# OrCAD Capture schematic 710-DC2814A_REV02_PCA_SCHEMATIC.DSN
size C
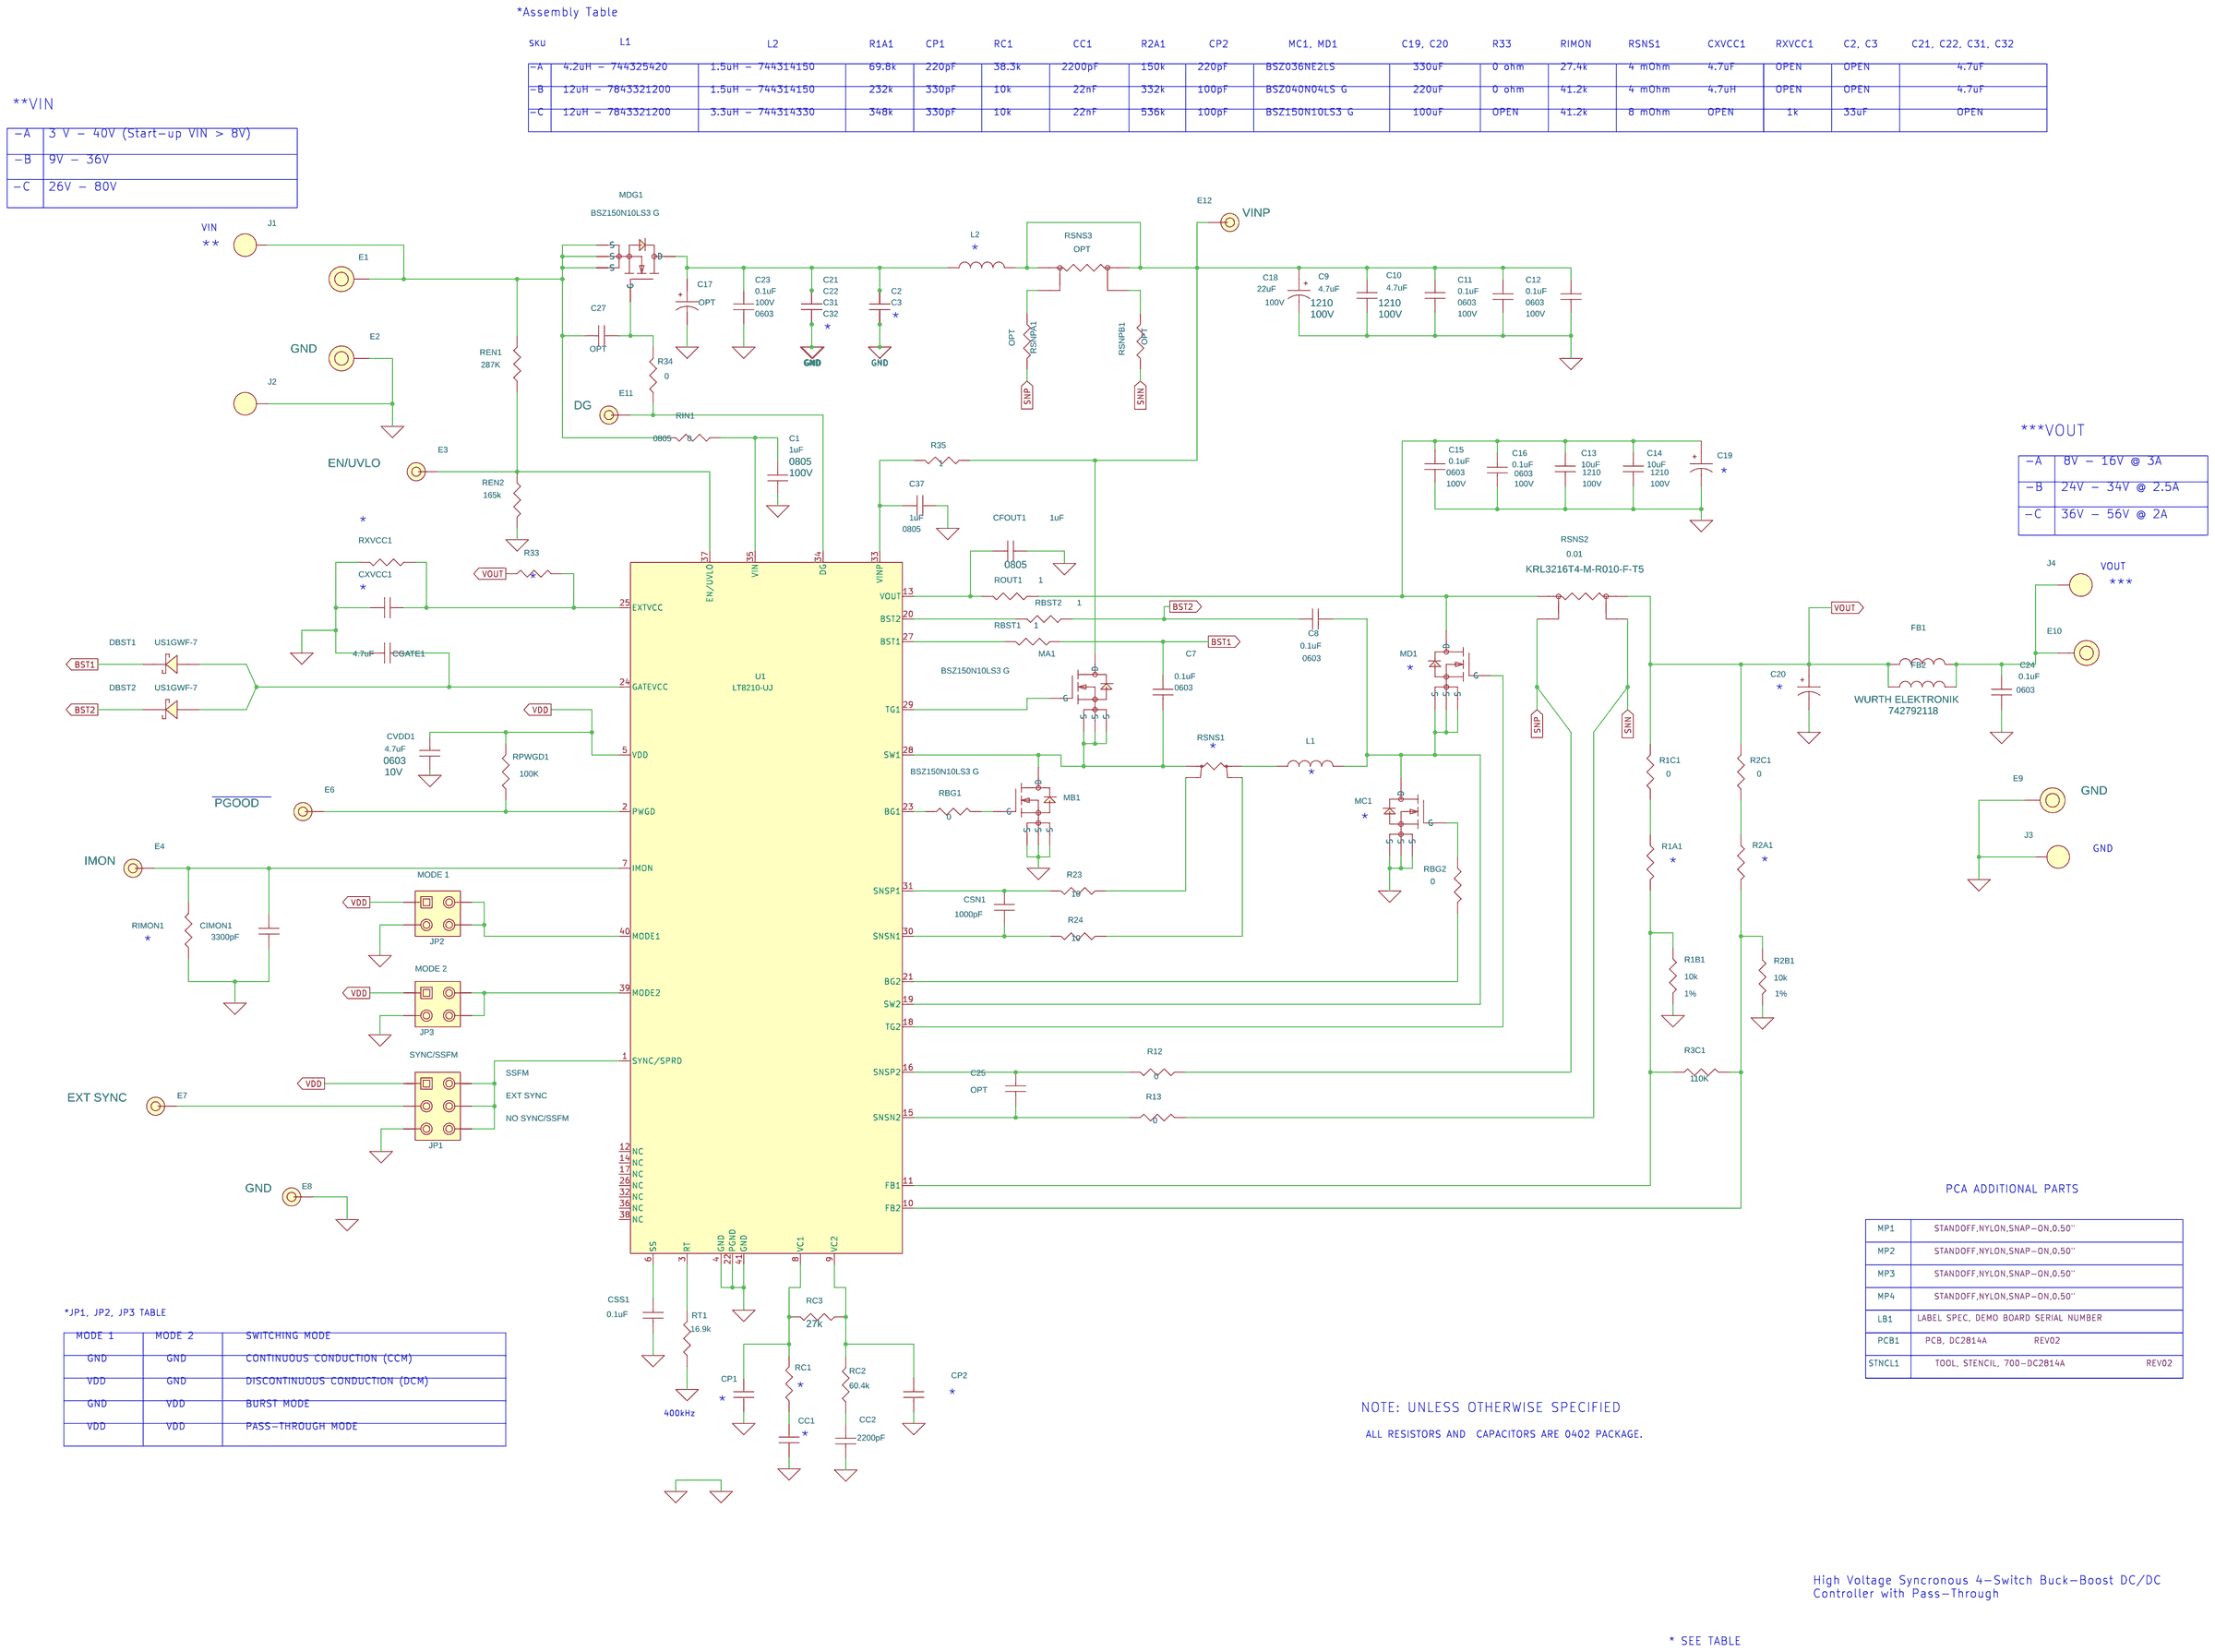
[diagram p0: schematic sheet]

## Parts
C1  1uF  [CC0805N]
C2  33uF  [CC2220N]
C3  33uF  [CC2220N]
C7  0.1uF  [CC0603N]
C8  0.1uF  [CC0603N]
C9  4.7uF  [CC1210N]
C10  4.7uF  [CC1210N]
C11  0.1uF  [CC0603N]
C12  0.1uF  [CC0603N]
C13  10uF  [CC1210N]
C14  10uF  [CC1210N]
C15  0.1uF  [CC0603N]
C16  0.1uF  [CC0603N]
C17  OPT  [USER_ASSIGNED]
C18  22uF  [PANASONIC_TGV_8X10.2]
C19  330uF  [SUNCON_CE-AX_10X10.2]
C20  330uF  [SUNCON_CE-AX_10X10.2]
C21  4.7uF  [CC1210N]
C22  4.7uF  [CC1210N]
C23  0.1uF  [CC0603N]
C24  0.1uF  [CC0603N]
C25  OPT  [CC0402L]
C27  OPT  [CC0402L]
C31  OPT  [CC1210N]
C32  OPT  [CC1210N]
C37  1uF  [CC0805N]
CC1  2200pF  [CC0402L]
CC2  2200pF  [CC0402L]
CFOUT1  1uF  [CC0805N]
CGATE1  4.7uF  [CC0402L]
CIMON1  3300pF  [CC0402L]
CP1  220pF  [CC0402L]
CP2  220pF  [CC0402L]
CSN1  1000pF  [CC0402L]
CSS1  0.1uF  [CC0402L]
CVDD1  4.7uF  [CC0603N]
CXVCC1  4.7uF  [CC0603N]
DBST1  US1GWF-7  [SOD-123F-N]
DBST2  US1GWF-7  [SOD-123F-N]
E1  TEST POINT  [MILLMAX2501]
E2  TEST POINT  [MILLMAX2501]
E3  TEST POINT  [MILLMAX2308]
E4  TEST POINT  [MILLMAX2308]
E6  TEST POINT  [MILLMAX2308]
E7  TEST POINT  [MILLMAX2308]
E8  TEST POINT  [MILLMAX2308]
E9  TEST POINT  [MILLMAX2501]
E10  TEST POINT  [MILLMAX2501]
E11  TEST POINT  [MILLMAX2308]
E12  TEST POINT  [MILLMAX2308]
FB1  600 OHMS @ 100MHz  [IND1206N]
FB2  600 OHMS @ 100MHz  [IND1206N]
J1  BANANA JACK  [KEY-575-4]
J2  BANANA JACK  [KEY-575-4]
J3  BANANA JACK  [KEY-575-4]
J4  BANANA JACK  [KEY-575-4]
JP1  HDR.  [HD2X3-079]
JP2  HDR  [HD2X2-079]
JP3  HDR  [HD2X2-079]
L1  4.2uH  [WURTH-744325420]
L2  3.3uH  [WURTH-7050]
LB1  LABEL  [895-0154_REV01]
MA1  BSZ150N10LS3 G  [INFINEON-PG-TSDSON-8]
MB1  BSZ150N10LS3 G  [INFINEON-PG-TSDSON-8]
MC1  BSZ036NE2LS  [INFINEON-PG-TSDSON-8-FL]
MD1  BSZ036NE2LS  [INFINEON-PG-TSDSON-8-FL]
MDG1  BSZ150N10LS3 G  [INFINEON-PG-TSDSON-8]
MP1  STANDOFF  [KEYSTONE_8829-8834]
MP2  STANDOFF  [KEYSTONE_8829-8834]
MP3  STANDOFF  [KEYSTONE_8829-8834]
MP4  STANDOFF  [KEYSTONE_8829-8834]
PCB1  PCB, DC2814A
R1A1  69.8k  [CR0402L]
R1B1  10k  [CR0402N]
R1C1  0  [CR0402L]
R2A1  549k  [CR0402L]
R2B1  10k  [CR0402N]
R2C1  0  [CR0402L]
R3C1  110K  [CR0402L]
R12  0  [CR0402L]
R13  0  [CR0402L]
R23  10  [CR0402N]
R24  10  [CR0402N]
R33  0  [CR0402L]
R34  0  [CR0402L]
R35  1  [CR0402N]
RBG1  0  [CR0402N]
RBG2  0  [CR0402N]
RBST1  1  [CR0402N]
RBST2  1  [CR0402N]
RC1  38.3k  [CR0402L]
RC2  60.4k  [CR0402L]
RC3  27k  [CR0402L]
REN1  287K  [CR0402L]
REN2  165k  [CR0402L]
RIMON1  41.2k  [CR0402L]
RIN1  0  [CR0805N]
ROUT1  1  [CR0402N]
RPWGD1  100K  [CR0402L]
RSNPA1  OPT  [CR0402L]
RSNPB1  OPT  [CR0402L]
RSNS1  0.004  [SUSUMU-KRL3216T4]
RSNS2  0.01  [0612]
RSNS3  0.01  [0612]
RT1  16.9k  [CR0603N]
RXVCC1  1k  [CR0603N]
STNCL1  TOOL, STENCIL, 700-DC2814A
U1  LT8210-UJ  [LTC-UJ-40-1728]
XJP1  SHUNT
XJP2  SHUNT
XJP3  SHUNT

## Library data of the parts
C1 C37 CFOUT1 = CAP: CAP.,1uF,X7S,100V,10%,0805,SOFT TERM.; CLASS: DISCRETE; Dielectric Type: X7S; FPLIST: CC0805N,CC0805L,CC0805M; Inventory Qty: 11206; Manufacturer: MURATA; Manufacturer PN: GRJ21BC72A105KE11L; PART_NUMBER: 150-3382; Package Size: 0805; Rated Voltage: 100V; Tolerance: 10%
C2 = CAP: CAP.,33uF,X7S,100V,20%,2220,AEC-Q200, PRELIM; CLASS: DISCRETE; Dielectric Type: X7S; FPLIST: CC2220N,CC2220L,CC2220M; Inventory Qty: 500; Manufacturer: TDK; Manufacturer PN: CAA572X7S2A336M; PART_NUMBER: 150-2658; Package Size: 2220; Package Type: Surface Mount, MLCC; Rated Voltage: 100V; Temperature Coefficient: X7S; Tolerance: 20%
C3 = CAP: CAP.,33uF,X7S,100V,20%,2220,AEC-Q200, PRELIM; CLASS: DISCRETE; Dielectric Type: X7S; Inventory Qty: 500; Manufacturer: TDK; Manufacturer PN: CAA572X7S2A336M; PART_NUMBER: 150-2658; Package Size: 2220; Package Type: Surface Mount, MLCC; Rated Voltage: 100V; Temperature Coefficient: X7S; Tolerance: 20%
C7 C8 C11 C12 C23 = CAP: CAP.,0.1uF,X7S,100V,10%,0603; CLASS: DISCRETE; Dielectric Type: X7S; FPLIST: CC0603N,CC0603L,CC0603M; Inventory Qty: 5600; Manufacturer: TAIYO YUDEN; Manufacturer PN: HMK107C7104KA-T; PART_NUMBER: 150-0493; Package Size: 0603; Rated Voltage: 100V; Tolerance: 10%
C9 C10 C21 C22 = CAP: CAP.,4.7uF,X7S,100V,20%,1210; CLASS: DISCRETE; Dielectric Type: X7S; FPLIST: CC1210N,CC1210L,CC1210M; Inventory Qty: 0; Manufacturer: TDK; Manufacturer PN: C3225X7S2A475M200AB; PART_NUMBER: 150-0486; Package Size: 1210; Rated Voltage: 100V; Tolerance: 20%
C13 C14 = CAP: CAP.,10uF,X7S,100V,10%,1210; CLASS: DISCRETE; Dielectric Type: X7S; Inventory Qty: 7175; Manufacturer: MURATA; Manufacturer PN: GRM32EC72A106KE05L; PART_NUMBER: 150-2537; Package Size: 1210; Package Type: Surface Mount, MLCC; Rated Voltage: 100V; Temperature Coefficient: X7S; Tolerance: 10%
C15 C16 C24 = CAP: CAP.,0.1uF,X7R,100V,10%,0603; CLASS: DISCRETE; Dielectric Type: X7R; FPLIST: CC0603N,CC0603L,CC0603M; Inventory Qty: 34836; Manufacturer: AVX; Manufacturer PN: 06031C104KAT2A; PART_NUMBER: 150-3294; Package Size: 0603; Rated Voltage: 100V; Tolerance: 10%
C17 = CAP_P_ALT: CAP.,OPTION,ALUM. ELECT.,SMD; CLASS: DISCRETE; PART_NUMBER: 150-0497; Package Type: SMD; UserField01: HVP Series
C18 = CAP_P_ALT: CAP.,22uF,ALUM. ELECT.,100V,20%,8x10.2mm SMD,AEC-Q200; CLASS: DISCRETE; Dielectric Type: ALUM. ELECT.; Inventory Qty: 0; Manufacturer: PANASONIC; Manufacturer PN: EEETG2A220UP; PART_NUMBER: 150-2536; Package Size: 8x10.2mm SMD; Rated Voltage: 100V; Tolerance: 20%; UserField01: HVP Series
C19 C20 = CAP_P_ALT: CAP.,330uF,ALUM. ELECT.,35V,20%,10x10.2mm SMD; CLASS: DISCRETE; Dielectric Type: ALUM. ELECT.; Inventory Qty: 0; Manufacturer: SUN ELECTRONIC INDUSTRIES CORP; Manufacturer PN: 35CE330AX; PART_NUMBER: 150-2342; Package Size: 10x10.2mm SMD; Rated Voltage: 35V; Tolerance: 20%
C25 C27 = CAP: CAP., OPTION, 0402; CLASS: DISCRETE; FPLIST: CC0402N,CC0402L,CC0402M; PART_NUMBER: 150-3148; Package Size: 0402; Package Type: SMD
C31 C32 = CAP: CAP., OPTION, 1210; CLASS: DISCRETE; FPLIST: CC1210N,CC1210L,CC1210M; PART_NUMBER: 150-3035; Package Size: 1210; Package Type: SMD
CC1 CC2 = CAP: CAP.,2200pF,X7R,16V,10%,0402; CLASS: DISCRETE; Dielectric Type: X7R; FPLIST: CC0402N,CC0402L,CC0402M; Inventory Qty: 6000; Manufacturer: AVX; Manufacturer PN: 0402YC222KAT2A; PART_NUMBER: 150-3196; Package Size: 0402; Rated Voltage: 16V; Tolerance: 10%
CGATE1 = CAP: CAP.,4.7uF,X5R,10V,10%,0402; CLASS: DISCRETE; Dielectric Type: X5R; FPLIST: CC0402N,CC0402L,CC0402M; Inventory Qty: 11209; Manufacturer: TDK; Manufacturer PN: C1005X5R1A475K050BC; PART_NUMBER: 150-2275; Package Size: 0402; Rated Voltage: 10V; Tolerance: 10%
CIMON1 = CAP: CAP.,3300pF,X7R,16V,10%,0402; CLASS: DISCRETE; Dielectric Type: X7R; FPLIST: CC0402N,CC0402L,CC0402M; Inventory Qty: 352; Manufacturer: AVX; Manufacturer PN: 0402YC332KAT2A; PART_NUMBER: 150-2337; Package Size: 0402; Rated Voltage: 16V; Tolerance: 10%
CP1 CP2 = CAP: CAP.,220pF,NP0,25V,10%,0402; CLASS: DISCRETE; Dielectric Type: NP0; FPLIST: CC0402N,CC0402L,CC0402M; Inventory Qty: 6794; Manufacturer: AVX; Manufacturer PN: 04023A221KAT2A; PART_NUMBER: 150-0348; Package Size: 0402; Rated Voltage: 25V; Tolerance: 10%
CSN1 = CAP: CAP.,1000pF,X7R,16V,10%,0402; CLASS: DISCRETE; Dielectric Type: X7R; FPLIST: CC0402N,CC0402L,CC0402M; Inventory Qty: 9944; Manufacturer: AVX; Manufacturer PN: 0402YC102KAT2A; PART_NUMBER: 150-3197; Package Size: 0402; Rated Voltage: 16V; Tolerance: 10%
CSS1 = CAP: CAP.,0.1uF,X7R,25V,10%,0402; CLASS: DISCRETE; Dielectric Type: X7R; FPLIST: CC0402N,CC0402L,CC0402M; Inventory Qty: 45380; Manufacturer: AVX; Manufacturer PN: 04023C104KAT2A; PART_NUMBER: 150-2276; Package Size: 0402; Rated Voltage: 25V; Tolerance: 10%
CVDD1 = CAP: CAP.,4.7uF,X5R,10V,10%,0603; CLASS: DISCRETE; Dielectric Type: X5R; FPLIST: CC0603N,CC0603L,CC0603M; Inventory Qty: 8100; Manufacturer: SAMSUNG; Manufacturer PN: CL10A475KP8NNNC; PART_NUMBER: 150-0243; Package Size: 0603; Rated Voltage: 10V; Tolerance: 10%
CXVCC1 = CAP: CAP.,4.7uF,X5R,16V,20%,0603; CLASS: DISCRETE; Dielectric Type: X5R; FPLIST: CC0603N,CC0603L,CC0603M; Inventory Qty: 23674; Manufacturer: MURATA; Manufacturer PN: GRM188R61C475MAAJD; PART_NUMBER: 150-0551; Package Size: 0603; Rated Voltage: 16V; Tolerance: 20%
DBST1 DBST2 = DIODE_SCHOTTKY_A_ALT: DIODE,RECT.,400V,1A,SOD123F,AEC-Q101; CLASS: DISCRETE; FPLIST: SOD-123F-N,SOD-123F-L,SOD-123F-M,SOD-123F; Inventory Qty: 470; Manufacturer: DIODES INC.; PART_NUMBER: 210-0335; Package Size: SOD-123F; Package Type: SOD123F; Rated Voltage: 100V; Rated Voltage or Zener Voltage: 400V
E1 E10 = TESTPOINT_.219_MILL-MAX_2501_A: TEST POINT,TURRET,0.094" MTG. HOLE,PCB 0.062" THICK; CLASS: IO; Inventory Qty: 455239; Manufacturer: MILL-MAX; Manufacturer PN: 2501-2-00-80-00-00-07-0; PART_NUMBER: 260-0003
E2 E9 = TESTPOINT_.219_MILL-MAX_2501_A: TEST POINT,TURRET,0.094" MTG. HOLE,PCB 0.062" THICK; CLASS: IO; Inventory Qty: 455239; Manufacturer: MILL-MAX; Manufacturer PN: 2501-2-00-80-00-00-07-0; PART_FIELD_01: GND; PART_NUMBER: 260-0003
E3 = TEST_POINT_.156_MILL-MAX_2308_B: TEST POINT,TURRET,0.064" MTG. HOLE,PCB 0.062" THICK; CLASS: IO; Inventory Qty: 841868; Manufacturer: MILL-MAX; Manufacturer PN: 2308-2-00-80-00-00-07-0; PART_FIELD_01: EN/UVLO; PART_NUMBER: 260-0004
E4 = TEST_POINT_.156_MILL-MAX_2308_B: TEST POINT,TURRET,0.064" MTG. HOLE,PCB 0.062" THICK; CLASS: IO; Inventory Qty: 841868; Manufacturer: MILL-MAX; Manufacturer PN: 2308-2-00-80-00-00-07-0; PART_FIELD_01: IMON; PART_NUMBER: 260-0004
E6 = TEST_POINT_.156_MILL-MAX_2308_B: TEST POINT,TURRET,0.064" MTG. HOLE,PCB 0.062" THICK; CLASS: IO; Inventory Qty: 841868; Manufacturer: MILL-MAX; Manufacturer PN: 2308-2-00-80-00-00-07-0; PART_FIELD_01: PGOOD; PART_NUMBER: 260-0004
E7 = TEST_POINT_.156_MILL-MAX_2308_B: TEST POINT,TURRET,0.064" MTG. HOLE,PCB 0.062" THICK; CLASS: IO; Inventory Qty: 841868; Manufacturer: MILL-MAX; Manufacturer PN: 2308-2-00-80-00-00-07-0; PART_FIELD_01: EXT SYNC; PART_NUMBER: 260-0004
E8 = TEST_POINT_.156_MILL-MAX_2308_B: TEST POINT,TURRET,0.064" MTG. HOLE,PCB 0.062" THICK; CLASS: IO; Inventory Qty: 841868; Manufacturer: MILL-MAX; Manufacturer PN: 2308-2-00-80-00-00-07-0; PART_FIELD_01: GND; PART_NUMBER: 260-0004
E11 = TEST_POINT_.156_MILL-MAX_2308_B: TEST POINT,TURRET,0.064" MTG. HOLE,PCB 0.062" THICK; CLASS: IO; Inventory Qty: 841868; Manufacturer: MILL-MAX; Manufacturer PN: 2308-2-00-80-00-00-07-0; PART_FIELD_01: DG; PART_NUMBER: 260-0004
E12 = TEST_POINT_.156_MILL-MAX_2308_B: TEST POINT,TURRET,0.064" MTG. HOLE,PCB 0.062" THICK; CLASS: IO; Inventory Qty: 841868; Manufacturer: MILL-MAX; Manufacturer PN: 2308-2-00-80-00-00-07-0; PART_FIELD_01: VINP; PART_NUMBER: 260-0004
FB1 FB2 = IND_ALT: IND.,600 OHMS @ 100MHz,FERRITE BEAD,25%,2.5A,70mOHMS,1206; CLASS: DISCRETE; Inventory Qty: 0; Manufacturer: WURTH ELEKTRONIK; Manufacturer PN: 742792118; PART_NUMBER: 200-0577; Package Size: 1206; Tolerance: 25%
J1-J4 = BANANA_KEYSTONE-575-4_C: CONN.,BANANA JACK,FEMALE,THT,NON-INSULATED, SWAGE; CLASS: IO; Inventory Qty: 175474; Manufacturer: KEYSTONE; Manufacturer PN: 575-4; PART_NUMBER: 250-0428
JP1 = HDR2X3_ALT1: CONN.,HDR.,MALE,2x3,2mm,VERT, STR, THT; 10th Part Field: SSFM; 11th Part Field: EXT SYNC; 12th Part Field: NO SYNC/SSFM; 9th Part Field: SYNC/SSFM; CLASS: IO; Inventory Qty: 29512; Manufacturer: SAMTEC; Manufacturer PN: TMM-103-02-L-D; PART_NUMBER: 250-0423
JP2 = HDR2X2_ALT1: CONN.,HDR,MALE,2x2,2mm,VERT, STR, THT,10u" Au; 9th Part Field: MODE 1; CLASS: IO; Inventory Qty: 11882; Manufacturer: SAMTEC; Manufacturer PN: TMM-102-02-L-D; PART_NUMBER: 250-0424
JP3 = HDR2X2_ALT1: CONN.,HDR,MALE,2x2,2mm,VERT, STR, THT,10u" Au; 9th Part Field: MODE 2; CLASS: IO; Inventory Qty: 11882; Manufacturer: SAMTEC; Manufacturer PN: TMM-102-02-L-D; PART_NUMBER: 250-0424
L1 = IND_ALT: IND.,4.2uH,PWR,20%,11A,7.1mOhm,1050; CLASS: DISCRETE; Inventory Qty: 0; Manufacturer: WURTH ELEKTRONIK; Manufacturer PN: 744325420; PART_NUMBER: 200-0578; Package Size: 1050; Tolerance: 20%
L2 = IND_ALT: IND.,3.3uH,PWR,20%,9A,9mOHMS,7050; CLASS: DISCRETE; Inventory Qty: 0; Manufacturer: WURTH ELEKTRONIK; Manufacturer PN: 744314330; PART_NUMBER: 200-0659; Package Size: 7050; Tolerance: 20%
LB1 = BLANK_LABEL: LABEL SPEC, DEMO BOARD SERIAL NUMBER; Inventory Qty: 0; Manufacturer: BRADY; Manufacturer PN: THT-96-717-10; PART_NUMBER: 895-0154
MA1 MB1 MDG1 = 5P_N-CH_TYPE1D: XSTR.,MOSFET, N-CH,100V,40V,PG-TSDSON-8; CLASS: DISCRETE; Inventory Qty: 0; Manufacturer: INFINEON; PART_NUMBER: 240-0340; Package Type: PG-TSDSON-8; Polarity: N Channel; Rated Voltage: 100V
MC1 MD1 = 5P_N-CH_TYPE1D: XSTR.,MOSFET, N-CH,25V,16A,PG-TSDSON-8; CLASS: DISCRETE; Inventory Qty: 0; Manufacturer: INFINEON; PART_NUMBER: 240-0338; Package Size: 8-PowerTDFN; Package Type: PG-TSDSON-8; Polarity: N-Channel; Rated Voltage: 25V
MP1-MP4 = BLANK_MECHANICAL_PART: STANDOFF,NYLON,SNAP-ON,0.50"; CLASS: MECHANICAL PART; Inventory Qty: 202956; Manufacturer: KEYSTONE; Manufacturer PN: 8833; PART_NUMBER: 763-0007
PCB1 = BLANK_PCB_PART: BOM Notes: REV02; CLASS: DISCRETE; Inventory Qty: 0; Manufacturer: PHASE 3; Manufacturer PN: 600-DC2814A; PART_NUMBER: 600-DC2814A
R1A1 = RES: RES.,69.8k OHMS,1%,1/16W,0402,AEC-Q200; CLASS: DISCRETE; FPLIST: CR0402N,CR0402L,CR0402M; Inventory Qty: 9945; Manufacturer: VISHAY; Manufacturer PN: CRCW040269K8FKED; PART_NUMBER: 100-2936; Package Size: 0402; Rated Power: 1/16W; Temperature Coefficient: 100ppm; Tolerance: 1%
R1B1 R2B1 = RES: RES.,10k OHMS,1%,1/16W,0402,AEC-Q200; CLASS: DISCRETE; FPLIST: CR0402N,CR0402L,CR0402M; Inventory Qty: 70038; Manufacturer: VISHAY; Manufacturer PN: CRCW040210K0FKED; PART_NUMBER: 100-2545; Package Size: 0402; Rated Power: 1/16W; Temperature Coefficient: 100ppm/C; Tolerance: 1%
R1C1 R2C1 R12 R13 R33 R34 RBG1 RBG2 = RES: RES.,0 OHM,1/16W,0402; CLASS: DISCRETE; FPLIST: CR0402N,CR0402L,CR0402M; Inventory Qty: 188771; Manufacturer: ROHM; Manufacturer PN: MCR01MZPJ000; PART_NUMBER: 100-0215; Package Size: 0402; Rated Power: 1/16W
R2A1 = RES: RES.,549k OHMS,1%,1/16W,0402; CLASS: DISCRETE; FPLIST: CR0402N,CR0402L,CR0402M; Inventory Qty: 0; Manufacturer: NIC; Manufacturer PN: NRC04F5493TRF; PART_NUMBER: 100-2930; Package Size: 0402; Rated Power: 1/16W; Temperature Coefficient: 100ppm; Tolerance: 1%
R3C1 = RES: RES.,110k OHMS,1%,1/16W,0402,AEC-Q200; CLASS: DISCRETE; FPLIST: CR0402N,CR0402L,CR0402M; Inventory Qty: 980; Manufacturer: Vishay; Manufacturer PN: CRCW0402110KFKED; PART_NUMBER: 100-0550; Package Size: 0402; Rated Power: 1/16W; Temperature Coefficient: +/-100PPM; Tolerance: 1%
R23 R24 = RES: RES.,10 OHMS,1%,1/16W,0402,AEC-Q200; CLASS: DISCRETE; FPLIST: CR0402N,CR0402L,CR0402M; Inventory Qty: 41168; Manufacturer: NIC; Manufacturer PN: NRC04F10R0TRF; PART_NUMBER: 100-0325; Package Size: 0402; Rated Power: 1/16W; Temperature Coefficient: 100ppm; Tolerance: 1%
R35 RBST1 RBST2 ROUT1 = RES: RES.,1 OHM,1%,1/16W,0402,+/-100ppm,AEC-Q200; CLASS: DISCRETE; FPLIST: CR0402N,CR0402L,CR0402M; Inventory Qty: 28307; Manufacturer: VISHAY; Manufacturer PN: CRCW04021R00FKED; PART_NUMBER: 100-0241; Package Size: 0402; Rated Power: 1/16W; Temperature Coefficient: +/-100ppm; Tolerance: 1%
RC1 = RES: RES.,38.3k OHMS,1%,1/16W,0402,AEC-Q200; CLASS: DISCRETE; Inventory Qty: 39748; Manufacturer: VISHAY; Manufacturer PN: CRCW040238K3FKED; PART_NUMBER: 100-0968; Package Size: 0402; Rated Power: 1/16W; Temperature Coefficient: 100ppm; Tolerance: 1%
RC2 = RES: RES.,60.4k OHMS,1%,1/16W,0402; CLASS: DISCRETE; FPLIST: CR0402N,CR0402L,CR0402M; Inventory Qty: 4855; Manufacturer: NIC; Manufacturer PN: NRC04F6042TRF; PART_NUMBER: 100-2803; Package Size: 0402; Rated Power: 1/16W; Temperature Coefficient: 100ppm; Tolerance: 1%
RC3 = RES: RES.,27k OHMS,1%,1/16W,0402; CLASS: DISCRETE; FPLIST: CR0402N,CR0402L,CR0402M; Inventory Qty: 0; Manufacturer: YAGEO; Manufacturer PN: RC0402FR-0727KL; PART_NUMBER: 100-0047; Package Size: 0402; Rated Power: 1/16W; Temperature Coefficient: 100ppm/C; Tolerance: 1%
REN1 = RES: RES.,287k OHMS,1%,1/16W,0402,AEC-Q200; CLASS: DISCRETE; FPLIST: CR0402N,CR0402L,CR0402M; Inventory Qty: 9860; Manufacturer: VISHAY; Manufacturer PN: CRCW0402287KFKED; PART_NUMBER: 100-2867; Package Size: 0402; Rated Power: 1/16W; Temperature Coefficient: 100PPM; Tolerance: 1%
REN2 = RES: RES.,165k OHMS,1%,1/16W,0402,AEC-Q200; CLASS: DISCRETE; FPLIST: CR0402N,CR0402L,CR0402M; Inventory Qty: 30732; Manufacturer: VISHAY; Manufacturer PN: CRCW0402165KFKED; PART_NUMBER: 100-0518; Package Size: 0402; Rated Power: 1/16W; Temperature Coefficient: 100ppm; Tolerance: 1%
RIMON1 = RES: RES.,41.2k OHMS,1%,1/16W,0402,AEC-Q200; CLASS: DISCRETE; FPLIST: CR0402N,CR0402L,CR0402M; Inventory Qty: 0; Manufacturer: VISHAY; Manufacturer PN: CRCW040241K2FKED; PART_NUMBER: 100-2706; Package Size: 0402; Rated Power: 1/16W; Temperature Coefficient: 100ppm/C; Tolerance: 1%
RIN1 = RES: RES.,0 OHM,1/8W,0805; CLASS: DISCRETE; FPLIST: CR0805N,CR0805L,CR0805M; Inventory Qty: 86528; Manufacturer: VISHAY; Manufacturer PN: CRCW08050000Z0EA; PART_NUMBER: 100-0024; Package Size: 0805; Rated Power: 1/8W
RPWGD1 = RES: RES.,100k OHMS,1%,1/16W,0402,AEC-Q200; CLASS: DISCRETE; FPLIST: CR0402N,CR0402L,CR0402M; Inventory Qty: 92806; Manufacturer: NIC; Manufacturer PN: NRC04F1003TRF; PART_NUMBER: 100-0601; Package Size: 0402; Rated Power: 1/16W; Temperature Coefficient: 100PPM; Tolerance: 1%
RSNPA1 RSNPB1 = RES: RES., OPTION, 0402; CLASS: DISCRETE; FPLIST: CR0402N,CR0402L,CR0402M; PART_NUMBER: 100-0357; Package Size: 0402
RSNS1 = RES_4_PIN: RES.,0.004 OHM,1%,1W,1206, 4-TERM.,SENSE, AEC-Q200; CLASS: DISCRETE; Inventory Qty: 0; Manufacturer: SUSUMU; Manufacturer PN: KRL3216T4-M-R004-F-T1; PART_NUMBER: 100-2820; Package Size: 1206, 4-TERM.; Rated Power: 1W; Temperature Coefficient: +/-50ppm; Tolerance: 1%
RSNS2 = RSENSE_4PIN: RES.,0.01 OHM,1%,1W,1206, 4-TERM.,SENSE, AEC-Q200; BOM Notes: NO STUFF RSNS3; CLASS: DISCRETE; Inventory Qty: 0; Manufacturer: SUSUMU; Manufacturer PN: KRL3216T4-M-R010-F-T5; PART_NUMBER: 100-1021; Package Size: 1206, 4-TERM.; Rated Power: 1W; Tolerance: 1%
RSNS3 = RSENSE_4PIN: RES.,0.01 OHM,1%,1W,1206, 4-TERM.,SENSE, AEC-Q200; BOM Notes: NO STUFF RSNS3; CLASS: DISCRETE; Inventory Qty: 0; Manufacturer: SUSUMU; Manufacturer PN: KRL3216T4-M-R010-F-T5; PART_FIELD_01: OPT; PART_NUMBER: 100-1021; Package Size: 1206, 4-TERM.; Rated Power: 1W; Tolerance: 1%
RT1 = RES: RES.,16.9k OHMS,1%,1/10W,0603,AEC-Q200; CLASS: DISCRETE; FPLIST: CR0603N,CR0603L,CR0603M; Inventory Qty: 30620; Manufacturer: NIC; Manufacturer PN: NRC06F1692TRF; PART_NUMBER: 100-2653; Package Size: 0603; Rated Power: 1/10W; Temperature Coefficient: 100ppm; Tolerance: 1%
RXVCC1 = RES: RES.,1k OHM,1%,1/10W,0603,AEC-Q200; CLASS: DISCRETE; FPLIST: CR0603N,CR0603L,CR0603M; Inventory Qty: 80293; Manufacturer: VISHAY; Manufacturer PN: CRCW06031K00FKEA; PART_NUMBER: 100-2422; Package Size: 0603; Rated Power: 1/10W; Temperature Coefficient: 100ppm; Tolerance: 1%
STNCL1 = BLANK_STENCIL_PART: BOM Notes: REV02; CLASS: DISCRETE; Inventory Qty: 0; Manufacturer: LINEAR TECH.; Manufacturer PN: 830-DC2814A; PART_NUMBER: 830-DC2814A
U1 = LT8210-UJ: IC,100V, Buck-Boost Controller,QFN-40 (6x6); CLASS: IC; Inventory Qty: 0; Manufacturer: LINEAR TECH.; Manufacturer PN: LT8210EUJ#PBF; PART_NUMBER: LT8210EUJ#PBF; Package Size: 6X6 QFN; Package Type: QFN-40 (6x6)
XJP1-XJP3 = SHUNT_2MM_C: CONN.,SHUNT,FEMALE,2-POS,2mm; CLASS: IO; Inventory Qty: 72144; Manufacturer: SAMTEC; Manufacturer PN: 2SN-BK-G; PART_NUMBER: 250-0419

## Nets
GND: C1.1 C2.2 C3.2 C9.2 C10.2 C11.1 C12.1 C13.2 C14.2 C15.1 C16.1 C17.2 C18.2 C19.2 C20.2 C21.2 C22.2 C23.2 C24.2 C31.2 C32.2 C37.1 CC1.2 CC2.2 CFOUT1.1 CGATE1.2 CIMON1.2 CP1.2 CP2.2 CSS1.2 CVDD1.2 CXVCC1.2 E2.1 E8.1 E9.1 J2.1 J3.1 JP1.5 JP2.3 JP3.3 MB1.1(S) MB1.2(S) MB1.3(S) MC1.1(S) MC1.2(S) MC1.3(S) R1B1.2 R2B1.2 REN2.2 RIMON1.2 RT1.2 RXVCC1.2 U1.4(GND) U1.22(PGND) U1.41(GND)
VDD: CVDD1.1 JP1.1 JP2.1 JP3.1 RPWGD1.1 U1.5(VDD)
BST1: C7.1 DBST1.1(C) RBST1.1
BST2: C8.1 DBST2.1(C) RBST2.1
SNN: R13.2 RSNPB1.1 RSNS2.2
SNP: R12.2 RSNPA1.1 RSNS2.4
VOUT: C20.1 FB1.1 FB2.1 R1C1.1 R2C1.1 R33.1 RSNS2.1
N17009346: CC1.1 RC1.2
N17465905: C8.2 L1.2 MC1.5(D) MD1.1(S) MD1.2(S) MD1.3(S) U1.19(SW2)
N17465907: C13.1 C14.1 C15.2 C16.2 C19.1 MD1.5(D) ROUT1.1 RSNS2.3
N17654739: R23.2 RSNS1.4
N17656525: CSN1.2 R24.1 U1.30(SNSN1)
N17656821: R24.2 RSNS1.3
N17708049: C24.1 E10.1 FB1.2 FB2.2 J4.1
N17804280: C27.1 E1.1 J1.1 MDG1.1(S) MDG1.2(S) MDG1.3(S) REN1.1 RIN1.1
N17841959: E6.1 RPWGD1.2 U1.2(PWGD)
N17844598: CIMON1.1 E4.1 RIMON1.1 U1.7(IMON)
N17844682: E7.1 JP1.3
N17868485: CP1.1 RC1.1 RC3.1 U1.8(VC1)
N17869654: R1A1.2 R1B1.1 R3C1.1 U1.11(FB1)
N17869668: R1A1.1 R1C1.2
N17916920: C2.1 C3.1 C17.1 C21.1 C22.1 C23.1 C31.1 C32.1 L2.1 MDG1.5(D)
N17979961: C9.1 C10.1 C11.2 C12.2 C18.1 E12.1 L2.2 MA1.5(D) R35.1 RSNS3.1 RSNS3.3
N18008210: RSNPB1.2 RSNS3.2
N18045167: CC2.1 RC2.2
N18045597: CP2.1 RC2.1 RC3.2 U1.9(VC2)
N18046372: CGATE1.1 DBST1.2(A) DBST2.2(A) U1.24(GATEVCC)
N18046482: CXVCC1.1 R33.2 RXVCC1.1 U1.25(EXTVCC)
N18047467: JP2.2 JP2.4 U1.40(MODE1)
N18047484: JP3.2 JP3.4 U1.39(MODE2)
N18050864: E11.1 R34.1 U1.34(DG)
N18051372: C37.2 R35.2 U1.33(VINP)
N18053205: R2A1.2 R2B1.1 R3C1.2 U1.10(FB2)
N18053219: R2A1.1 R2C1.2
N18093787: RBST2.2 U1.20(BST2)
N18094147: CFOUT1.2 ROUT1.2 U1.13(VOUT)
N18094171: RBST1.2 U1.27(BST1)
N18094221: MA1.4(G) U1.29(TG1)
N18094309: C7.2 MA1.1(S) MA1.2(S) MA1.3(S) MB1.5(D) RSNS1.2 U1.28(SW1)
N18095349: CSN1.1 R23.1 U1.31(SNSP1)
N18096084: RBG2.2 U1.21(BG2)
N18096199: C25.2 R13.1 U1.15(SNSN2)
N18096209: C25.1 R12.1 U1.16(SNSP2)
N18096793: MD1.4(G) U1.18(TG2)
N18097756: RT1.1 U1.3(RT)
N18100085: CSS1.1 U1.6(SS)
N18102990: RSNPA1.2 RSNS3.4
N18104379: C1.2 RIN1.2 U1.35(VIN)
N18105637: E3.1 REN1.2 REN2.1 U1.37(EN/UVLO)
N18117576: RBG1.1 U1.23(BG1)
N18127914: L1.1 RSNS1.1
N18131220: JP1.2 JP1.4 JP1.6 U1.1(SYNC/SPRD)
N18136109: C27.2 MDG1.4(G) R34.2
N18139017: MC1.4(G) RBG2.1
N18141622: MB1.4(G) RBG1.2

Not connected (* = marked no-connect by the designer): U1 12(NC) 14(NC) 17(NC) 26(NC) 32(NC) 36(NC) 38(NC)

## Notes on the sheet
- *Assembly Table
- L1
- SKU
- L2
- R1A1
- CP1
- RC1
- CC1
- R2A1
- CP2
- MC1, MD1
- C19, C20
- R33
- RIMON
- RSNS1
- CXVCC1
- RXVCC1
- C2, C3
- C21, C22, C31, C32
- -A
- 4.2uH - 744325420
- 1.5uH - 744314150
- 69.8k
- 220pF
- 38.3k
- 2200pF
- 150k
- 220pF
- BSZ036NE2LS
- 330uF
- 0 ohm
- 27.4k
- 4 mOhm
- 4.7uF
- OPEN
- OPEN
- 4.7uF
- -B
- 12uH - 7843321200
- 1.5uH - 744314150
- 232k
- 330pF
- 10k
- 22nF
- 332k
- 100pF
- BSZ040N04LS G
- 220uF
- 0 ohm
- 41.2k
- 4 mOhm
- 4.7uH
- OPEN
- OPEN
- 4.7uF
- **VIN
- -C
- 12uH - 7843321200
- 3.3uH - 744314330
- 348k
- 330pF
- 10k
- 22nF
- 536k
- 100pF
- BSZ150N10LS3 G
- 100uF
- OPEN
- 41.2k
- 8 mOhm
- OPEN
- 1k
- 33uF
- OPEN
- -A
- 3 V - 40V (Start-up VIN > 8V)
- -B
- 9V - 36V
- -C
- 26V - 80V
- VIN
- **
- *
- *
- *
- ***VOUT
- -A
- 8V - 16V @ 3A
- *
- -B
- 24V - 34V @ 2.5A
- *
- -C
- 36V - 56V @ 2A
- *
- VOUT
- *
- ***
- *
- *
- *
- *
- *
- GND
- *
- *
- *
- PCA ADDITIONAL PARTS
- *JP1, JP2, JP3 TABLE
- MODE 1
- MODE 2
- SWITCHING MODE
- GND
- GND
- CONTINUOUS CONDUCTION (CCM)
- VDD
- GND
- DISCONTINUOUS CONDUCTION (DCM)
- *
- *
- GND
- VDD
- BURST MODE
- *
- NOTE: UNLESS OTHERWISE SPECIFIED
- 400kHz
- VDD
- VDD
- PASS-THROUGH MODE
- *
- ALL RESISTORS AND  CAPACITORS ARE 0402 PACKAGE.
- High Voltage Syncronous 4-Switch Buck-Boost DC/DC
  Controller with Pass-Through
- * SEE TABLE
